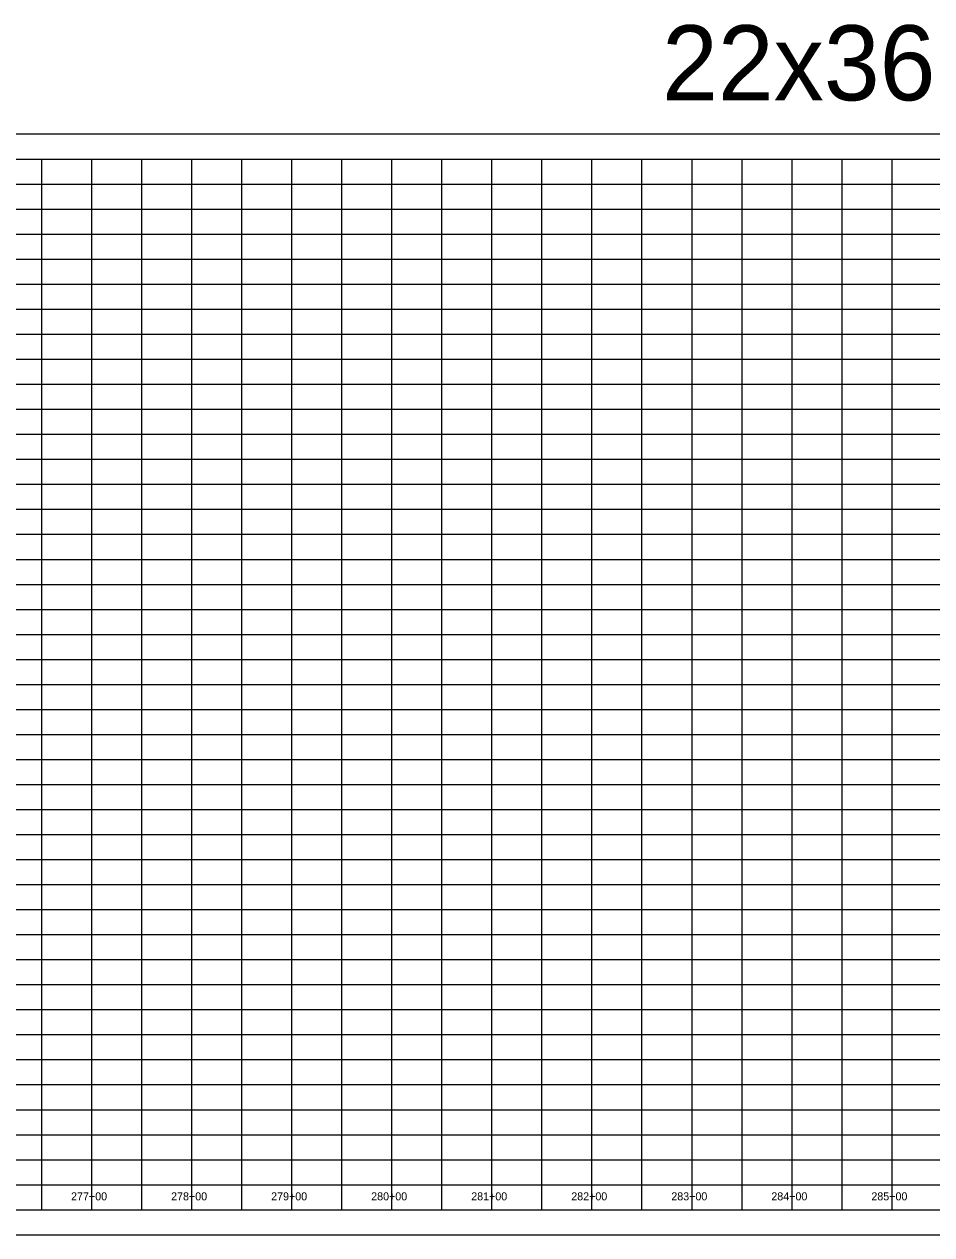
# Model space of a CAD drawing. Extents: x 1873632 to 1926512, y 813126 to 836257.
# Drawn here: x 1905995 to 1906903, y 830505 to 831714 of the extents above; entities that cross this region are included whole.
import ezdxf

# ---------------------------------------------------------------- set-up
doc = ezdxf.new("R2010")
doc.units = 0
for name, color, linetype in [('RD_DDB_StaTX', 7, 'Continuous'), ('RD_PD_WallFill', 7, 'Continuous'), ('RD_SHT_IplotShp', 7, 'Continuous')]:
    doc.layers.add(name, color=color, linetype=linetype)

msp = doc.modelspace()

# ---------------------------------------------------------------- linework, layer by layer
at = {"layer": 'RD_PD_WallFill'}
for p, q in [((1905062.9, 831579.6), (1910412.9, 831579.6)), ((1905062.9, 831579.6), (1906812.9, 831579.6)), ((1906012.9, 830529.6), (1906012.9, 831579.6)), ((1906012.9, 830529.6), (1906012.9, 831579.6)), ((1906062.9, 830529.6), (1906062.9, 831579.6)), ((1906062.9, 830529.6), (1906062.9, 831579.6)), ((1906112.9, 830529.6), (1906112.9, 831579.6)), ((1906112.9, 830529.6), (1906112.9, 831579.6)), ((1906162.9, 830529.6), (1906162.9, 831579.6)), ((1906162.9, 830529.6), (1906162.9, 831579.6)), ((1906212.9, 830529.6), (1906212.9, 831579.6)), ((1906212.9, 830529.6), (1906212.9, 831579.6)), ((1906262.9, 830529.6), (1906262.9, 831579.6)), ((1906262.9, 830529.6), (1906262.9, 831579.6)), ((1906312.9, 830529.6), (1906312.9, 831579.6)), ((1906312.9, 830529.6), (1906312.9, 831579.6)), ((1906362.9, 830529.6), (1906362.9, 831579.6)), ((1906362.9, 830529.6), (1906362.9, 831579.6)), ((1906412.9, 830529.6), (1906412.9, 831579.6)), ((1906412.9, 830529.6), (1906412.9, 831579.6)), ((1906462.9, 830529.6), (1906462.9, 831579.6)), ((1906462.9, 830529.6), (1906462.9, 831579.6)), ((1906512.9, 830529.6), (1906512.9, 831579.6)), ((1906512.9, 830529.6), (1906512.9, 831579.6)), ((1906562.9, 830529.6), (1906562.9, 831579.6)), ((1906562.9, 830529.6), (1906562.9, 831579.6)), ((1906612.9, 830529.6), (1906612.9, 831579.6)), ((1906612.9, 830529.6), (1906612.9, 831579.6)), ((1906662.9, 830529.6), (1906662.9, 831579.6)), ((1906662.9, 830529.6), (1906662.9, 831579.6)), ((1906712.9, 830529.6), (1906712.9, 831579.6)), ((1906712.9, 830529.6), (1906712.9, 831579.6)), ((1906762.9, 830529.6), (1906762.9, 831579.6)), ((1906762.9, 830529.6), (1906762.9, 831579.6)), ((1906812.9, 830529.6), (1906812.9, 831579.6)), ((1906812.9, 830529.6), (1906812.9, 831579.6)), ((1906862.9, 830529.6), (1906862.9, 831579.6)), ((1906862.9, 830529.6), (1906862.9, 831579.6)), ((1905512.9, 831554.6), (1910412.9, 831554.6)), ((1905512.9, 831554.6), (1910412.9, 831554.6)), ((1905512.9, 831529.6), (1910412.9, 831529.6)), ((1905512.9, 831504.6), (1910412.9, 831504.6)), ((1905512.9, 831479.6), (1910412.9, 831479.6)), ((1905512.9, 831454.6), (1910412.9, 831454.6)), ((1905062.9, 831429.6), (1910412.9, 831429.6)), ((1905062.9, 831404.6), (1910412.9, 831404.6)), ((1905062.9, 831379.6), (1910412.9, 831379.6)), ((1905062.9, 831354.6), (1910412.9, 831354.6)), ((1905062.9, 831329.6), (1910412.9, 831329.6)), ((1905062.9, 831304.6), (1910412.9, 831304.6)), ((1905062.9, 831279.6), (1910412.9, 831279.6)), ((1905062.9, 831254.6), (1910412.9, 831254.6)), ((1905062.9, 831229.6), (1910412.9, 831229.6)), ((1905062.9, 831204.6), (1910412.9, 831204.6)), ((1905062.9, 831179.6), (1910412.9, 831179.6)), ((1905062.9, 831154.6), (1910412.9, 831154.6)), ((1905062.9, 831129.6), (1910412.9, 831129.6)), ((1905062.9, 831104.6), (1910412.9, 831104.6)), ((1905062.9, 831079.6), (1910412.9, 831079.6)), ((1905062.9, 831054.6), (1910412.9, 831054.6)), ((1905062.9, 831029.6), (1910412.9, 831029.6)), ((1905062.9, 831004.6), (1910412.9, 831004.6)), ((1905062.9, 830979.6), (1910412.9, 830979.6)), ((1905062.9, 830954.6), (1910412.9, 830954.6)), ((1905062.9, 830929.6), (1910412.9, 830929.6)), ((1905062.9, 830904.6), (1910412.9, 830904.6)), ((1905062.9, 830879.6), (1910412.9, 830879.6)), ((1905062.9, 830854.6), (1910412.9, 830854.6)), ((1905062.9, 830829.6), (1910412.9, 830829.6)), ((1905062.9, 830804.6), (1910412.9, 830804.6)), ((1905062.9, 830779.6), (1910412.9, 830779.6)), ((1905062.9, 830754.6), (1910412.9, 830754.6)), ((1905062.9, 830729.6), (1910412.9, 830729.6)), ((1905062.9, 830704.6), (1910412.9, 830704.6)), ((1905062.9, 830679.6), (1910412.9, 830679.6)), ((1905062.9, 830654.6), (1910412.9, 830654.6)), ((1905062.9, 830629.6), (1910412.9, 830629.6)), ((1905062.9, 830604.6), (1910412.9, 830604.6)), ((1905062.9, 830579.6), (1910412.9, 830579.6)), ((1905062.9, 830554.6), (1910412.9, 830554.6)), ((1905062.9, 830529.6), (1910412.9, 830529.6)), ((1905062.9, 830529.6), (1910412.9, 830529.6))]:
    msp.add_line(p, q, dxfattribs=at)
at = {"layer": 'RD_SHT_IplotShp'}
msp.add_lwpolyline([(1905037.9, 830504.6), (1910437.9, 830504.6), (1910437.9, 831604.6), (1905037.9, 831604.6)], close=True, dxfattribs=at)

# ---------------------------------------------------------------- texts
at = {"layer": 'RD_DDB_StaTX'}
for s, p in [('277+00', (1906042.2, 830539)), ('278+00', (1906142.2, 830539)), ('279+00', (1906242.2, 830539)), ('280+00', (1906342.2, 830539)), ('281+00', (1906442.2, 830539)), ('282+00', (1906542.2, 830539)), ('283+00', (1906642.2, 830539)), ('284+00', (1906742.2, 830539)), ('285+00', (1906842.2, 830539))]:
    msp.add_text(s, height=8, dxfattribs=at).set_placement(p)
at = {"layer": 'RD_PD_WallFill'}
msp.add_text('22x36', height=75, dxfattribs=at).set_placement((1906633, 831638.3))
msp.add_text('22x36', height=75, dxfattribs=at).set_placement((1906633, 831638.3))

doc.saveas('drawing.dxf')
